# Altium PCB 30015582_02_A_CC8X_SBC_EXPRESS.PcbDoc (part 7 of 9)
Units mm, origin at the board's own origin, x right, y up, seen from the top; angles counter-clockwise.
Board outline 87 x 63 mm, 6 copper layers (Top Layer-L1, GND Plane-L2, Signal-L3, PWR/Signal-L4, GND Plane-L5, Bottom Layer-L6), stack 1.172 mm thick; 169 components, 171 nets, 693 pads, 391 vias.
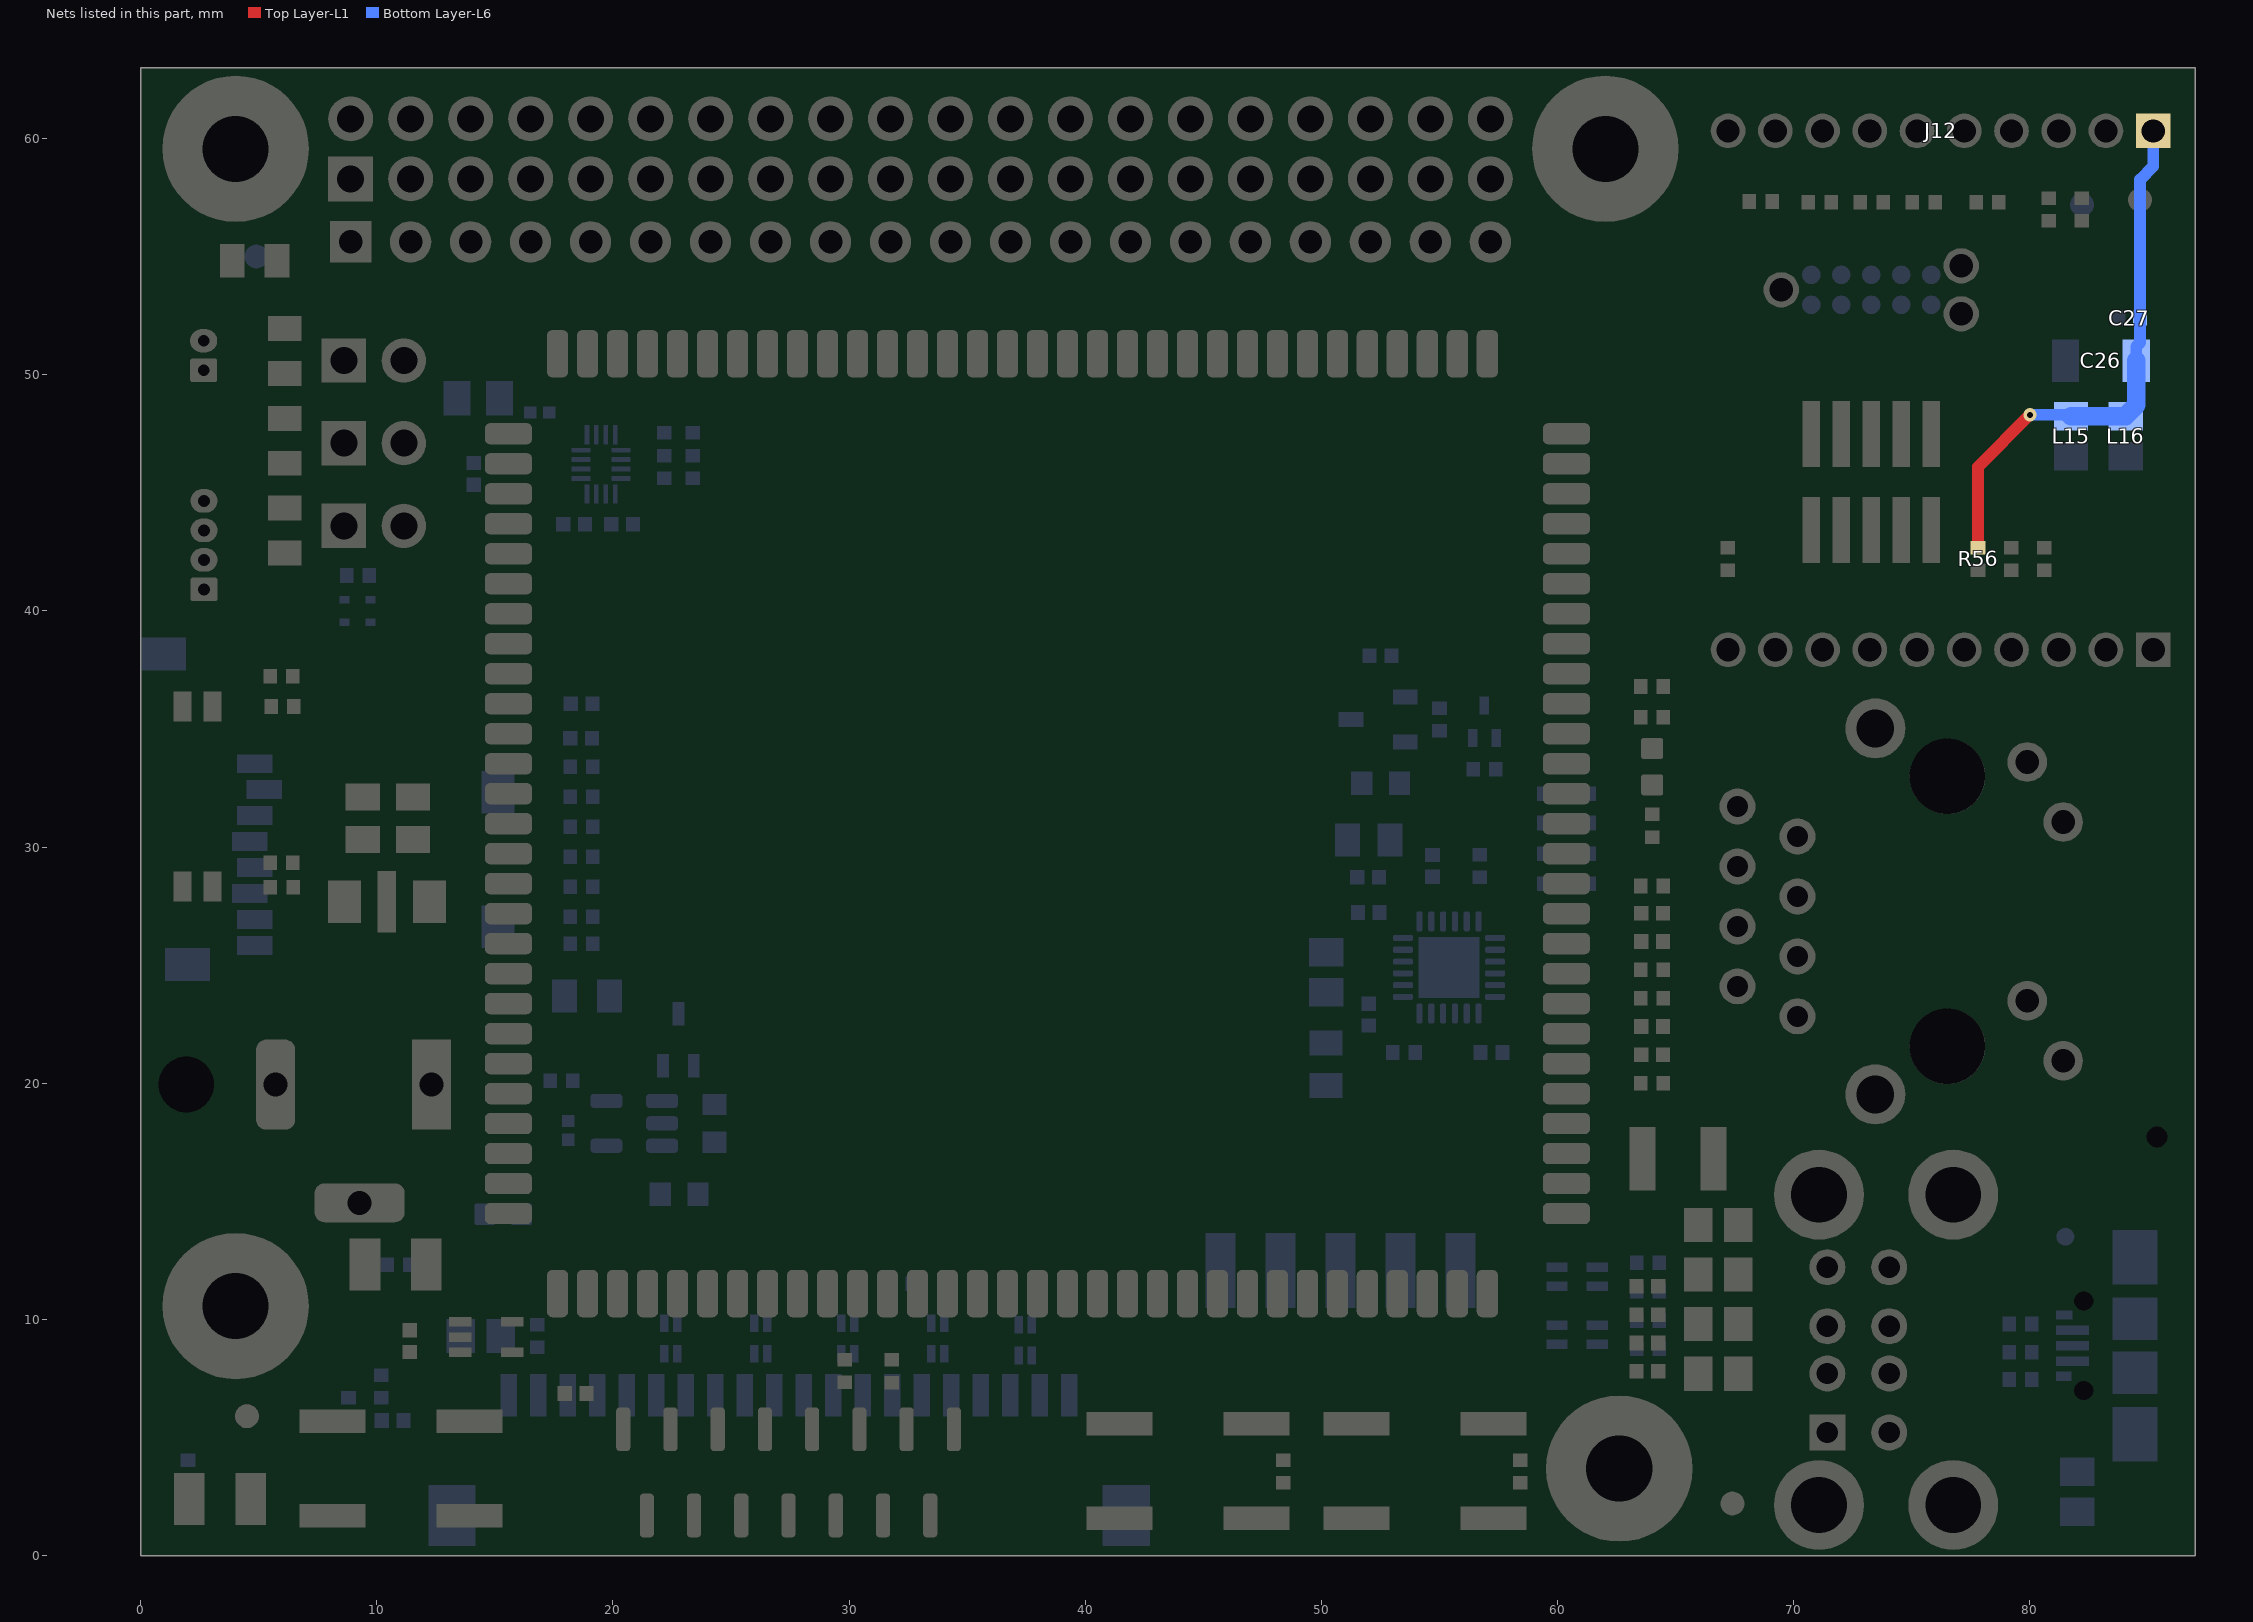
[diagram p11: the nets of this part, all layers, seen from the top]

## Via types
v1: diameter 0.56, hole 0.25, Top Layer-L1 to Bottom Layer-L6, 391 vias

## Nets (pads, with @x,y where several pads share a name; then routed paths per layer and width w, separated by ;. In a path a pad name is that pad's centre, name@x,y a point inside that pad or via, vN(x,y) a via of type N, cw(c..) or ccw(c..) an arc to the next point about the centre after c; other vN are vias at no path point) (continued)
XBEE_VCC: C26.1 C27.2 J12.1 L15.2 L16.2 R56.2 | length 23.5
  Top Layer-L1 w0.5: R56.2@77.8,42.68 77.8,46.1 v1(80,48.3)
  Bottom Layer-L6 w0.5: v1(80,48.3) L15.2@81.984,48.3 ; L15.2@81.684,48.3 L15.2@81.742,48.242 ; C26.1@84.5,50.6 84.5,51.2 84.66,51.36 C27.2@84.66,52.4 84.66,58.26 85.217,58.817 J12.1@85.217,60.325
  Bottom Layer-L6 w0.8: L15.2@81.742,48.242 84.028,48.242 L16.2@84.056,48.27 ; L16.2@84.056,48.242 L16.2@84.056,48.27 ; C26.1@84.5,50.6 84.5,48.714 L16.2@84.056,48.27
pads on no net: FIDUCIAL1.1 FIDUCIAL2.1 FIDUCIAL3.1 FIDUCIAL7.1 FIDUCIAL8.1 FIDUCIAL9.1 J2.3 J2.4 J6.7 J6.MNT1 J6.MNT2 J7.MT1 J7.MT21 J10.10 J10.11 J13.1 J13.2 J13.3 J13.4 J19.6 J19.7 J19.8 SWD.6 SWD.7 SWD.8 SWD.9 SWD.MT1 SWD.MT2 SWD.MT3 U2.11 U2.12 U2.13 U2.14 U2.15 U2.16 U3.4

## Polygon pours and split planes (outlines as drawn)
VCC_SCU_1V8 on Top Layer-L1 "Polysolid" (solid, remove dead copper, pour order 44): 6.2,29.1 6.2,30.232 7.1,31.132 7.1,35.5 6.9,35.7 6.2,35.7 6.2,36.2 7.5,36.2 8.4,37.1 10.8,37.1 10.9,37 10.9,34.7 10.3,34.1 8.6,34.1 8.2,33.7 8.2,31.3 6.7,29.8 6.7,29.1
3V3 on Top Layer-L1 "Polysolid" (solid, remove dead copper, pour order 28): 5.4,43.8 6.5,43.8 7.7,42.6 9.6,42.6 9.6,43.625 10.675,44.7 12,44.7 13.2,45.9 13.2,48.3 13.5,48.6 15.7,48.6 16.5,49.4 16.5,51.6 16.9,52 20.8,52 21.1,51.7 21.1,50.7 21.8,50.7 21.8,51.6 22.4,52.2 22.4,52.5 22.2,52.7 16.2,52.7 15.4,51.9 15.4,50.1 15.2,49.9 12.9,49.9 12.2,49.2 12.2,46.7 11,45.5 10.5,45.5 9.6,44.6 6.9,44.6 6.6,44.9 5.4,44.9
SHLD on Top Layer-L1 "Polysolid" (solid, remove dead copper, pour order 2): 69.8,0.9 77.2,0.9 79.1,2.8 79.1,15.4 77.6,16.9 76.7,16.9 74.8,15 74.8,13.8 77.3,11.3 77.3,6.2 75.2,4.1 71.3,4.1 69.8,2.6
VCC_SCU_1V8 on PWR/Signal-L4 "Polysolid" (solid, remove dead copper, pour order 46): 32,12.1 26,12.1 22.8,15.3 22.8,34.7 21.2,36.3 21.2,41.3 22.2,42.3 26.8,42.3 27.3,41.8 27.3,14.4 27.8,13.9 31.8,13.9 32.1,13.6 32.1,12.2
3V3_EXT on PWR/Signal-L4 "Polysolid" (solid, remove dead copper, pour order 40): 78,41.5 79.9,41.5 82.7,44.3 82.7,47.8 82.2,48.3 76.2,48.3 65,48.3 58.9,48.3 56.5,50.7 20.8,50.7 20.8,53.4 22.2,54.8 30.5,54.8 30.5,62.7 13.35,62.7 13.35,54.35 9.5,50.5 9.5,30.7 10.8,29.4 10.8,12.4 15.7,7.5 40.9,7.5 41.2,7.8 41.2,10.8 40.2,11.8 25.9,11.8 22.4,15.3 22.4,34.5 21,35.9 21,41.5 22.2,42.7 26.8,42.7 27.1,43 27.1,47.6 27.8,48.3 48.3,48.3 49.3,47.3 49.3,39.4 49.9,38.8 52.5,38.8 53,38.3 53,33.3 53.7,32.6 63.4,32.6 64.4,33.6 64.4,41 64.9,41.5 66.1,41.5 66.6,41 66.6,40.2 67.2,39.6 76.8,39.6 77.1,39.9 77.1,40.6
VCC_MCA on PWR/Signal-L4 "Polysolid" (solid, remove dead copper, pour order 36): 76,48.7 67.925,48.7 67.925,51.225 65.325,53.825 60.175,53.825 57.1,56.9 57.1,57.1 59.1,57.1 60.3,55.9 75.5,55.9 76.2,55.2 76.2,48.9
AVDD1 on PWR/Signal-L4 "Polysolid" (solid, remove dead copper, pour order 34): 49.3,21 50.8,19.5 63.8,19.5 65,20.7 65,29.3 64.7,29.6 63.3,29.6 63,29.3 63,24.5 61.5,23 49.5,23 49.3,22.8
3V3 on PWR/Signal-L4 "Polysolid" (solid, remove dead copper, pour order 24): 21.3,51.5 25.756,51.5 26.156,51.9 57.3,51.9 60.5,48.7 66.3,48.7 66.55,48.95 66.55,50.35 64.45,52.45 58.775,52.45 57.987,53.237 52.888,53.238 51.725,54.4 22.4,54.4 21.1,53.1 21.1,51.7
VIN on PWR/Signal-L4 "Polysolid" (solid, remove dead copper, pour order 12): 0.7,1.4 1.5,0.6 80.5,0.6 86.6,6.7 86.6,47.6 86.7,47.6 86.7,57.4 85.7,58.4 75.6,58.4 75.3,58.1 75.3,57.1 76.7,55.7 76.7,49.3 77.3,48.7 82.5,48.7 83.1,48.1 83.1,44.1 79.9,40.9 78.1,40.9 77.6,40.4 77.6,37.4 77.6,35.6 78,35.2 79.8,35.2 82.7,32.3 82.7,15.1 81.3,13.7 60.7,13.7 54.2,7.2 15.4,7.2 10.3,12.3 10.3,29 8.9,30.4 8.9,50.5 11.7,53.3 12.9,54.5 12.9,61.5 11.9,62.5 6.1,62.5 0.7,57.1 0.7,29
3V3_ETH0 on PWR/Signal-L4 "Polysolid" (solid, remove dead copper, pour order 0): 49.275,23.825 49.275,38.025 49.725,38.475 52.45,38.475 52.775,38.15 52.775,32.75 53.275,32.25 61.7,32.25 62.325,31.625 62.325,24.225 61.275,23.175 49.925,23.175
3V3 on Bottom Layer-L6 "Polysolid" (solid, remove dead copper, pour order 48): 64.8,39.6 64.8,49.3 65.2,49.7 66.3,49.7 66.6,49.4 66.6,40.2 65.8,39.4 65,39.4
VCC_SCU_1V8 on Bottom Layer-L6 "Polysolid" (solid, remove dead copper, pour order 42): 9.5,36.4 17.6,36.4 17.8,36.6 19.7,36.6 20.1,36.2 21.8,36.2 22,36.4 22,38.7 21.2,39.5 13.4,39.5 12,38.1 9.5,38.1 9.3,37.9 9.3,36.6
5V_CC8X on Bottom Layer-L6 "Polysolid" (solid, remove dead copper, pour order 26): 10.9,46.5 13.3,46.5 13.6,46.8 15,46.8 15.7,47.5 15.7,49 16.3,49.6 16.9,49.6 17.1,49.4 17.1,48.3 17.5,48.3 17.5,48.9 17.7,49.1 19.1,49.1 19.3,49.3 19.3,49.823 18.923,50.2 16.2,50.2 15.6,49.6 15,49.6 15,48.2 14.8,48 14.2,48 13.6,47.4 12.5,47.4 12.1,47.8 10.9,47.8
XBEE_VCC on Bottom Layer-L6 "Polysolid" (solid, remove dead copper, pour order 50): 79.7,47.7 85,47.7 85.2,47.9 85.2,57.9 85.8,58.5 85.8,60.4 85.4,60.8 84.8,60.8 84.6,60.6 84.6,59.1 84.1,58.6 84.1,53.3 84.4,53 84.4,52.1 83.9,51.6 83.9,49.2 83.6,48.9 79.8,48.9 79.5,48.6 79.5,47.9
GND on GND Plane-L2 (split plane): 86.49,0.51 0.51,0.51 0.51,62.49 86.49,62.49
GND on GND Plane-L5 (split plane): 86.49,0.51 0.51,0.51 0.51,62.49 86.49,62.49

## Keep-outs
Keep-Out Layer:
  lines w0.25: 0,39.45 0,63 87,63 87,0 0,0 0,39.575

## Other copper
Top Layer-L1:
  region net VIN: 11.95,9.25 12.15,9.05 12.15,8.775 12.325,8.6 12.65,8.6 12.8,8.75 12.8,9.575 12.925,9.7 14,9.7 14,10.1 12.05,10.1 11.8,9.85 11.1,9.85 11.1,9.25
  region net 1V8_EXT: 6.075,54.275 6.75,54.95 9.35,54.95 9.35,56.3 6.675,56.3 5.575,55.2 5.575,54.275
  region net VCC_MCA: 0.8,47.2 0.925,47.075 2.85,47.075 4.7,48.925 4.7,50.425 5.9,51.625 5.9,52.45 5.875,52.475 5.35,52.475 3.775,50.9 3.775,49.55 3,48.775 1.025,48.775 0.8,48.55
  region net 3V3_EXT: 2.375,43.9 4,43.9 4.925,42.975 6.775,42.975 7.725,42.025 7.725,41.65 4.825,41.65 3.575,42.9 2.375,42.9 2.1,43.175 2.1,43.625
  region net NetFIL1_1: 11.4,26.3 11.4,29.1 11.6,29.3 12.9,29.3 13.1,29.1 13.1,26.3 12.9,26.1 11.6,26.1
  region net VIN: 7.8,30.5 7.8,26.8 7.9,26.7 9.3,26.7 9.4,26.8 9.4,29.313 9.915,29.828 12.028,29.828 12.2,30 12.2,30.7 8,30.7
  region net GND: 10.059,31.9 10.059,33.3 9.959,33.4 8.859,33.4 8.759,33.3 8.759,31.9
  region net GND: 12.2,31.9 12.2,33.3 12.1,33.4 11,33.4 10.9,33.3 10.9,31.9
  region net GND: 63.75,18.075 62.45,18.075 62.325,17.95 62.325,15.675 62.45,15.55 63.75,15.55
  region net SHLD: 70,17.9 72.9,20.8 73.5,20.8 74.75,19.55 74.75,17.725 75.275,17.2 76.9,17.2 78.1,16 78.1,14.55 76.925,13.375 70.925,13.375 68.6,15.7 66.4,15.7 66.4,17.9
  region net NetFIL1_1: 11.9,18.4 11.6,18.7 11.6,26.5 11.8,26.7 12.8,26.7 13,26.5 13,18.4
  region net GND: 63,10 62.8,10.2 61.7,10.2 61.6,10.3 61.6,10.8 61.7,10.9 62.6,10.9 63.1,11.4 63.6,11.4 63.6,10
  region net GND: 63.6,7.55 61.675,7.55 61.6,7.625 61.6,8.35 61.7,8.45 62.575,8.45 63.15,9.025 63.6,9.025
  text "30015582-02_TOP" at 86.3,40 h1.1 r90
Signal-L3:
  text ".Layer_Name" at 27,-4.175 h2.54
PWR/Signal-L4:
  region net 3V3_EXT: 66.45,48 66.725,48.275 66.725,50.55 64.625,52.65 58.825,52.65 58.05,53.425 54.875,53.425 53.7,54.6 53.7,56.025 54.15,56.475 55.05,56.475 55.425,56.1 55.425,55.5 56.5,54.425 58.5,54.425 59.325,53.6 65.25,53.6 67.7,51.15 67.7,48.25 68.025,47.925
  text ".Layer_Name" at 24.575,-4.325 h2.54
Bottom Layer-L6:
  rectangle net NetJ7_19: 16.55,7.075 17.1,8.85
  region net GND: 82.189,1.4 82.189,2.3 83.089,2.3 83.6,2.811 83.6,14.3 83.8,14.5 86.1,14.5 86.2,14.4 86.2,3.7 83.9,1.4
  region net 3V3_EXT: 52.925,33.45 53.025,33.55 53.025,34.775 53.925,34.775 54.35,35.2 55.3,35.2 55.325,35.175 55.325,34.775 56.5,33.6 56.5,33 54.65,33 53.85,32.2 52.925,32.2
  region net 3V3_ETH0: 49.475,25.325 49.475,26.775 49.575,26.875 50.8,26.875 50.925,26.75 50.925,25.325
  region net AVDD1: 49.5,24 49.5,21.8 50.9,21.8 50.9,24
  text "30015582-02_BOT" at 84.582,20.066 h1.1 r270
  text ".Layer_Name" at 20.864,-4.552 h2.54
GND Plane-L2 (plane layer: these items are gaps in the copper):
  text ".Layer_Name" at 24.689,-4.827 h2.54
  text "Negative Image" at 23.175,-8.05 h2.54
GND Plane-L5 (plane layer: these items are gaps in the copper):
  text ".Layer_Name" at 24.775,-4.75 h2.54
  text "Negative Image" at 23.175,-8.05 h2.54

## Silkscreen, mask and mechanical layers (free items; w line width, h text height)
Top Overlay:
  drawing of 16 lines, arcs and shapes, not listed
  text "COIN CELL" at 4.3,53.5 h1.5 r270
  text "EXPANSION HEADER" at 10.89,53.018 h1.5
  text "CONSOLE" at 4.3,45.4 h1.5 r270
  text "Close" at 8.3,41.5 h1 r270
  text "Close" at 9.4,41.5 h1 r270
  text "Open" at 10.5,41.5 h1 r270
  text "SW1.2" at 11.5,41.5 h1 r270
  text "XBEE MODULE" at 68.1,39.9 h1.5
  text "Close" at 8.3,39.1 h1 r270
  text "Open" at 9.4,39.1 h1 r270
  text "Open" at 10.5,39.1 h1 r270
  text "SW1.1" at 11.5,39.1 h1 r270
  text "USB" at 8.3,36.6 h1 r270
  text "MicroSD" at 9.4,36.6 h1 r270
  text "eMMC" at 10.5,36.6 h1 r270
  text "BOOT" at 11.5,36.4 h1 r270
  text "10/100 ETH" at 66.04,35.56 h1.5
  text "BOOT" at 4.826,33.528 h1.5 r270
  text "PWR - 5V" at 0.762,25.019 h1.5
  text "5VDC" at 1.406,19.637 h1.4
  text "USB HOST" at 79.248,15.621 h1.5
  text "ConnectCore for i.MX8X SOM" at 18.639,8.763 h1.5
  text "RESET" at 42.568,7.255 h1.5
  text "ON/OFF" at 52.705,7.239 h1.5
  text "USER  BUTTON" at 7.75,6.975 h1.5
  text "MIPI DSI" at 35.022,5.885 h1.5
  text "USER LED" at 1.6,3.8 h1.5
Bottom Overlay:
  text "MICRO SD" at 16.383,39.37 h1.5
  text "USB DEVICE" at 85.5,14.8 h1.5
  text "Touch controller" at 58,14.1 h1.5
  text "LVDS" at 20.9,8.6 h1.5
  text ".Layer_Name" at 20.864,-4.552 h2.54
Top Paste:
  text ".Layer_Name" at 20.864,-4.552 h2.54
Bottom Paste:
  text ".Layer_Name" at 20.864,-4.552 h2.54
Top Solder:
  text ".Layer_Name" at 20.864,-4.552 h2.54
Bottom Solder:
  text ".Layer_Name" at 20.864,-4.552 h2.54
Board Outline:
  the board outline again, w0.2
Top Assembly:
  drawing of 53 lines, arcs and shapes, not listed
  text "1. Manufacture in accordance with IPC-6012, class 2. Inspect to IPC-A-600, class 2." at -17.381,81.17 h3.17
  text ".Layer_Name" at 20.864,-4.552 h2.54
  text "CAD GENERATED:" at 52.68,-9.22 h1.27
  text ".pcb_File_Name_No_Path" at 68.174,-9.22 h2.17
  text "EXCEPT AS MAY BE OTHERWISE PROVIDED BY" at -46.38,-13.284 h2.17
  text "WIRELESS DESIGN SERVICES" at 47.6,-14.808 h2.54
  text "CONTRACT, THIS DOCUMENT IS THE PROPERTY" at -46.38,-15.316 h2.17
  text "OF DIGI INTERNATIONAL.  IF RELEASED TO OTHER" at -46.38,-17.348 h2.17
  text "11001 Bren Road East" at 47.6,-18.364 h2.54
  text "SOURCES, IT SHALL BE RECEIVED BY SUCH" at -46.38,-19.38 h2.17
  text "SOURCES IN TOTAL CONFIDENCE AND SHALL NOT" at -46.38,-21.412 h2.17
  text "Minnetonka, MN 55343" at 48.108,-21.92 h2.54
  text "BE RELEASED TO ANY THIRD PARTY OR PARTIES," at -46.38,-23.444 h2.17
  text "NOR USED FOR MANUFACTURE OR SALE OF THE" at -46.38,-25.476 h2.17
  text "ARTICLES WITHOUT PRIOR WRITTEN" at -46.38,-27.508 h2.17
  text "DIGI International" at 39.123,-27.775 h2.54
  text "AUTHORIZATION." at -46.38,-29.54 h2.17
  text "Connect Core 8X" at 36.998,-31.625 h2.54
  text "SBC EXPRESS" at 40.259,-35.687 h2.54
  text "ENGINEER" at -46.888,-36.144 h1.27
  text "J.Anzola" at -30.124,-37.16 h1.27
  text "PCB DESIGNER" at -46.888,-41.224 h1.27
  text "SIZE" at 6.452,-41.224 h1.27
  text "CAGE NO." at 14.58,-41.224 h1.27
  text "PCB NO." at 42.52,-41.224 h1.27
  text "REV." at 104.496,-41.224 h1.27
  text "DIGI: 55002011-01" at 54.133,-43.04 h2.54
  text "DATE" at -46.888,-45.796 h1.27
  text "B" at 6.96,-45.796 h2.54
  text ".VariantRevision" at 104.496,-45.796 h2.54
  text ".Print_Date" at -30.124,-46.812 h1.27
  text "JIRA EPIC:" at -46.888,-50.876 h1.27
  text "CC8X-10" at -30.124,-52.4 h1.27
  text ".Print_Scale" at 4.42,-52.4 h1.27
  text "SVN HEAD REV:" at 29.82,-52.4 h1.27
  text ".VersionControl_RevNumber" at 45.568,-52.4 h1.27
  text "SHEET:" at 67.92,-52.4 h1.27
  text "1 OF 2" at 86.462,-52.4 h1.27
Bottom Assembly:
  drawing of 53 lines, arcs and shapes, not listed
  text "CUTOUT" at 45.085,41.402 h1.91
  text ".Layer_Name" at 57.785,-4.445 h2.54
  text ".pcb_File_Name_No_Path" at -4.318,-9.525 h2.17
  text "CAD GENERATED:" at 11.176,-9.525 h1.27
  text "EXCEPT AS MAY BE OTHERWISE PROVIDED BY" at 110.236,-13.589 h2.17
  text "WIRELESS DESIGN SERVICES" at 16.256,-15.113 h2.54
  text "CONTRACT, THIS DOCUMENT IS THE PROPERTY" at 110.236,-15.621 h2.17
  text "OF DIGI INTERNATIONAL.  IF RELEASED TO OTHER" at 110.236,-17.653 h2.17
  text "11001 Bren Road East" at 16.256,-18.669 h2.54
  text "SOURCES, IT SHALL BE RECEIVED BY SUCH" at 110.236,-19.685 h2.17
  text "SOURCES IN TOTAL CONFIDENCE AND SHALL NOT" at 110.236,-21.717 h2.17
  text "Minnetonka, MN 55343" at 15.748,-22.225 h2.54
  text "BE RELEASED TO ANY THIRD PARTY OR PARTIES," at 110.236,-23.749 h2.17
  text "NOR USED FOR MANUFACTURE OR SALE OF THE" at 110.236,-25.781 h2.17
  text "ARTICLES WITHOUT PRIOR WRITTEN" at 110.236,-27.813 h2.17
  text "DIGI International" at 24.732,-28.08 h2.54
  text "AUTHORIZATION." at 110.236,-29.845 h2.17
  text "Connect Core 8X" at 25.781,-32.004 h2.54
  text "SBC EXPRESS" at 22.479,-36.068 h2.54
  text "ENGINEER" at 110.744,-36.449 h1.27
  text "J.Anzola" at 93.98,-37.465 h1.27
  text "REV." at -40.64,-41.529 h1.27
  text "PCB NO." at 21.336,-41.529 h1.27
  text "CAGE NO." at 49.276,-41.529 h1.27
  text "SIZE" at 57.404,-41.529 h1.27
  text "PCB DESIGNER" at 110.744,-41.529 h1.27
  text "DIGI: 55002011-01" at 9.722,-43.345 h2.54
  text ".VariantRevision" at -40.64,-46.101 h2.54
  text "B" at 56.896,-46.101 h2.54
  text "DATE" at 110.744,-46.101 h1.27
  text ".Print_Date" at 93.98,-47.117 h1.27
  text "JIRA EPIC:" at 110.744,-51.181 h1.27
  text "SHEET:" at -4.064,-52.705 h1.27
  text ".VersionControl_RevNumber" at 18.288,-52.705 h1.27
  text "SVN HEAD REV:" at 34.036,-52.705 h1.27
  text ".Print_Scale" at 59.436,-52.705 h1.27
  text "CC8X-10" at 93.98,-52.705 h1.27
  text "2 of 2" at -22.428,-52.883 h1.27
PCB Name:
  text "CC8X SBC Express" at 18.5,69.9 h2.54
Sheet Graphics:
  drawing of 499 lines, arcs and shapes, not listed
  text "2" at 44.774,94.272 h4.57
  text "1" at 260.674,94.272 h4.57
  text "1. Manufacture in accordance with IPC-6012, class 2. Inspect to IPC-A-600, class 2." at 190,88 h4.44
  text "2. Manufacturing process and materials used must comply with / ROHS directive 2002/95/EC." at 190,78 h4.44
  text "3. Laminate and prepreg shall be per IPC-4101/126 / Dk shall be 4.2-4.5, Tg of 170°C or higher. / Material thicknesses and dielectric constant are critical items." at 190,64 h4.44
  text "4. Top and Bottom layer starting copper weight is 1 oz." at 190,58 h4.44
  text "5. Apply E.N.I.G. to all exposed copper per IPC-4552." at 190,52 h4.44
  text "6. Solder mask registration shall be ±25.4µm (1mil). Thickness / not to exceed 20.32µm (0.8mil). / COLOR: BLUE" at 190,38 h4.44
  text "B" at -58.299,33.058 h7.11
  text "B" at 357.753,33.058 h7.11
  text "7. Silkscreen Color: White silkscreen that encroaches on component pads." at 190,32 h4.44
  text "8. Gerber file format: 274-X with 2/4 accuracy (XX.XXXX) / Gerber and drill files generated in inches." at 190,22 h4.44
  text "9. Maximum warp and twist per IPC-6012 of 0.75% inch/inch." at 190,18 h4.44
  text "10. Vendor markings to appear on silkscreen or solder mask layers only." at 188,14 h4.44
  text "11. All boards to be 100% electrically tested." at 188,10 h4.44
  text "12. Copper thieving is not allowed within board outline.  Thieving may be placed in the array." at 188,6 h4.44
  text "13. Panel array to be approved by Digi." at 188,2 h4.44
  text "14. All drilled holes are specified as finished hole size." at 188,-2 h4.44
  text "15. Slot/Cutout tolerance ±0.005 inch when applicable." at 188,-6 h4.44
  text "16. Controlled Impedances listed in table." at 188.539,-11.365 h4.44
  text "17.  All via/plated holes have a tolerance of ±76.2µm (3mil) unless otherwise specified. / Non-plated holes have a ±38.1µm tolerance unless otherwise specified." at 188,-22 h4.44
  text "18.  Total thickness is 47.5mil (1.2mm) +/- 10%." at 188,-26 h4.44
  text "19.  PCB material shall be IT-180A" at 188,-32 h4.44
  text "T" at 163.048,-44.431 h6.02
  text "r" at 165.461,-44.431 h6.02
  text "a" at 167.186,-44.431 h6.02
  text "c" at 169.599,-44.431 h6.02
  text "e" at 171.668,-44.431 h6.02
  text "l" at 175.461,-44.431 h6.02
  text "a" at 176.841,-44.431 h6.02
  text "y" at 179.255,-44.431 h6.02
  text "e" at 181.668,-44.431 h6.02
  text "r" at 184.427,-44.431 h6.02
  text "R" at 187.981,-44.431 h6.02
  text "e" at 190.739,-44.431 h6.02
  text "f" at 193.498,-44.431 h6.02
  text "e" at 195.222,-44.431 h6.02
  text "r" at 197.981,-44.431 h6.02
  text "e" at 199.705,-44.431 h6.02
  text "n" at 202.463,-44.431 h6.02
  text "c" at 205.222,-44.431 h6.02
  text "e" at 207.291,-44.431 h6.02
  text "l" at 211.084,-44.431 h6.02
  text "a" at 212.463,-44.431 h6.02
  text "y" at 214.877,-44.431 h6.02
  text "e" at 217.291,-44.431 h6.02
  text "r" at 220.05,-44.431 h6.02
  text "(" at 221.774,-44.431 h6.02
  text "s" at 223.498,-44.431 h6.02
  text ")" at 225.567,-44.431 h6.02
  text "I" at 229.189,-44.431 h6.02
  text "m" at 230.569,-44.431 h6.02
  text "p" at 234.706,-44.431 h6.02
  text "e" at 237.465,-44.431 h6.02
  text "d" at 240.224,-44.431 h6.02
  text "a" at 242.982,-44.431 h6.02
  text "n" at 245.396,-44.431 h6.02
  text "c" at 248.155,-44.431 h6.02
  text "e" at 250.224,-44.431 h6.02
  text "(" at 254.017,-44.431 h6.02
  text "Ω" at 255.741,-44.431 h6.02
  text ")" at 259.189,-44.431 h6.02
  text "W" at 263.818,-44.431 h6.02
  text "1" at 268.646,-44.431 h6.02
  text "(" at 272.094,-44.431 h6.02
  text "m" at 273.818,-44.431 h6.02
  text "m" at 277.956,-44.431 h6.02
  text ")" at 282.094,-44.431 h6.02
  text "S" at 287.02,-44.431 h6.02
  text "1" at 289.434,-44.431 h6.02
  text "(" at 292.882,-44.431 h6.02
  text "m" at 294.606,-44.431 h6.02
  text "m" at 298.744,-44.431 h6.02
  text ")" at 302.882,-44.431 h6.02
  text "D" at 307.797,-44.431 h6.02
  text "1" at 310.901,-44.431 h6.02
  text "(" at 314.349,-44.431 h6.02
  text "m" at 316.073,-44.431 h6.02
  text "m" at 320.211,-44.431 h6.02
  text ")" at 324.349,-44.431 h6.02
  text "1" at 183.825,-51.328 h6.02
  text "2" at 206.68,-51.328 h6.02
  text "5" at 229.189,-51.328 h6.02
  text "0" at 231.603,-51.328 h6.02
  text "+" at 234.017,-51.328 h6.02
  text "/" at 236.431,-51.328 h6.02
  text "-" at 238.5,-51.328 h6.02
  text "1" at 240.224,-51.328 h6.02
  text "0" at 242.638,-51.328 h6.02
  text "%" at 245.051,-51.328 h6.02
  text "0" at 274.207,-51.328 h6.02
  text "." at 276.621,-51.328 h6.02
  text "1" at 278,-51.328 h6.02
  text "6" at 280.414,-51.328 h6.02
  text "5" at 282.828,-51.328 h6.02
  text "16" at 144.78,-55.88 h4.44
  text "3" at 183.825,-58.224 h6.02
  text "2" at 206.68,-58.224 h6.02
  text "5" at 229.189,-58.224 h6.02
  text "0" at 231.603,-58.224 h6.02
  text "+" at 234.017,-58.224 h6.02
  text "/" at 236.431,-58.224 h6.02
  text "-" at 238.5,-58.224 h6.02
  text "1" at 240.224,-58.224 h6.02
  text "0" at 242.638,-58.224 h6.02
  text "%" at 245.051,-58.224 h6.02
  text "0" at 274.207,-58.224 h6.02
  text "." at 276.621,-58.224 h6.02
  text "1" at 278,-58.224 h6.02
  text "2" at 280.414,-58.224 h6.02
  text "2" at 282.828,-58.224 h6.02
  text "6" at 183.825,-65.121 h6.02
  text "5" at 206.68,-65.121 h6.02
  text "5" at 229.189,-65.121 h6.02
  text "0" at 231.603,-65.121 h6.02
  text "+" at 234.017,-65.121 h6.02
  text "/" at 236.431,-65.121 h6.02
  text "-" at 238.5,-65.121 h6.02
  text "1" at 240.224,-65.121 h6.02
  text "0" at 242.638,-65.121 h6.02
  text "%" at 245.051,-65.121 h6.02
  text "0" at 274.207,-65.121 h6.02
  text "." at 276.621,-65.121 h6.02
  text "1" at 278,-65.121 h6.02
  text "6" at 280.414,-65.121 h6.02
  text "5" at 282.828,-65.121 h6.02
  text "1" at 183.825,-72.017 h6.02
  text "2" at 206.68,-72.017 h6.02
  text "9" at 229.189,-72.017 h6.02
  text "0" at 231.603,-72.017 h6.02
  text "+" at 234.017,-72.017 h6.02
  text "/" at 236.431,-72.017 h6.02
  text "-" at 238.5,-72.017 h6.02
  text "1" at 240.224,-72.017 h6.02
  text "0" at 242.638,-72.017 h6.02
  text "%" at 245.051,-72.017 h6.02
  text "0" at 274.207,-72.017 h6.02
  text "." at 276.621,-72.017 h6.02
  text "1" at 278,-72.017 h6.02
  text "2" at 280.414,-72.017 h6.02
  text "7" at 282.828,-72.017 h6.02
  text "0" at 294.985,-72.017 h6.02
  text "." at 297.398,-72.017 h6.02
  text "1" at 298.778,-72.017 h6.02
  text "2" at 301.191,-72.017 h6.02
  text "7" at 303.605,-72.017 h6.02
  text "LAYER STACK TABLE" at -33.23,-78.155 h4.44
  text "3" at 183.825,-78.914 h6.02
  text "2" at 206.68,-78.914 h6.02
  text "9" at 229.189,-78.914 h6.02
  text "0" at 231.603,-78.914 h6.02
  text "+" at 234.017,-78.914 h6.02
  text "/" at 236.431,-78.914 h6.02
  text "-" at 238.5,-78.914 h6.02
  text "1" at 240.224,-78.914 h6.02
  text "0" at 242.638,-78.914 h6.02
  text "%" at 245.051,-78.914 h6.02
  text "0" at 274.207,-78.914 h6.02
  text "." at 276.621,-78.914 h6.02
  text "1" at 278,-78.914 h6.02
  text "0" at 280.414,-78.914 h6.02
  text "2" at 282.828,-78.914 h6.02
  text "0" at 294.985,-78.914 h6.02
  text "." at 297.398,-78.914 h6.02
  text "1" at 298.778,-78.914 h6.02
  text "5" at 301.191,-78.914 h6.02
  text "2" at 303.605,-78.914 h6.02
  text "Layer" at -31.88,-82.902 h1.52
  text "Name" at -21.468,-82.902 h1.52
  text "Material" at 3.925,-82.902 h1.52
  text "Thickness" at 25.763,-82.902 h1.52
  text "Constant" at 42.269,-82.902 h1.52
  text "Board Layer Stack" at 56.743,-82.902 h1.52
  text "6" at 183.825,-85.811 h6.02
  text "5" at 206.68,-85.811 h6.02
  text "9" at 229.189,-85.811 h6.02
  text "0" at 231.603,-85.811 h6.02
  text "+" at 234.017,-85.811 h6.02
  text "/" at 236.431,-85.811 h6.02
  text "-" at 238.5,-85.811 h6.02
  text "1" at 240.224,-85.811 h6.02
  text "0" at 242.638,-85.811 h6.02
  text "%" at 245.051,-85.811 h6.02
  text "0" at 274.207,-85.811 h6.02
  text "." at 276.621,-85.811 h6.02
  text "1" at 278,-85.811 h6.02
  text "2" at 280.414,-85.811 h6.02
  text "7" at 282.828,-85.811 h6.02
  text "0" at 294.985,-85.811 h6.02
  text "." at 297.398,-85.811 h6.02
  text "1" at 298.778,-85.811 h6.02
  text "2" at 301.191,-85.811 h6.02
  text "7" at 303.605,-85.811 h6.02
  text "1" at -31.88,-85.95 h1.52
  text "Top Overlay" at -21.468,-85.95 h1.52
  text "2" at -31.88,-88.998 h1.52
  text "Top Solder" at -21.468,-88.998 h1.52
  text "Solder Resist" at 3.925,-88.998 h1.52
  text "0.40mil" at 25.763,-88.998 h1.52
  text "3.5" at 42.269,-88.998 h1.52
  text "3" at -31.88,-92.046 h1.52
  text "Top Layer-L1" at -21.468,-92.046 h1.52
  text "Copper" at 3.925,-92.046 h1.52
  text "1.89mil" at 25.763,-92.046 h1.52
  text "1" at 183.825,-92.707 h6.02
  text "2" at 206.68,-92.707 h6.02
  text "1" at 229.189,-92.707 h6.02
  text "0" at 231.603,-92.707 h6.02
  text "0" at 234.017,-92.707 h6.02
  text "+" at 236.431,-92.707 h6.02
  text "/" at 238.844,-92.707 h6.02
  text "-" at 240.913,-92.707 h6.02
  text "1" at 242.638,-92.707 h6.02
  text "0" at 245.051,-92.707 h6.02
  text "%" at 247.465,-92.707 h6.02
  text "0" at 274.207,-92.707 h6.02
  text "." at 276.621,-92.707 h6.02
  text "1" at 278,-92.707 h6.02
  text "1" at 280.414,-92.707 h6.02
  text "4" at 282.828,-92.707 h6.02
  text "0" at 294.985,-92.707 h6.02
  text "." at 297.398,-92.707 h6.02
  text "1" at 298.778,-92.707 h6.02
  text "7" at 301.191,-92.707 h6.02
  text "8" at 303.605,-92.707 h6.02
  text "4" at -31.88,-95.094 h1.52
  text "Dielectric 1" at -21.468,-95.094 h1.52
  text "FR-4" at 3.925,-95.094 h1.52
  text "4.92mil" at 25.763,-95.094 h1.52
  text "4.2" at 42.269,-95.094 h1.52
  text "5" at -31.88,-98.142 h1.52
  text "GND Plane-L2" at -21.468,-98.142 h1.52
  text "Copper" at 3.925,-98.142 h1.52
  text "1.10mil" at 25.763,-98.142 h1.52
  text "3" at 183.825,-99.604 h6.02
  text "2" at 206.68,-99.604 h6.02
  text "1" at 229.189,-99.604 h6.02
  text "0" at 231.603,-99.604 h6.02
  text "0" at 234.017,-99.604 h6.02
  text "+" at 236.431,-99.604 h6.02
  text "/" at 238.844,-99.604 h6.02
  text "-" at 240.913,-99.604 h6.02
  text "1" at 242.638,-99.604 h6.02
  text "0" at 245.051,-99.604 h6.02
  text "%" at 247.465,-99.604 h6.02
  text "0" at 274.207,-99.604 h6.02
  text "." at 276.621,-99.604 h6.02
  text "1" at 278,-99.604 h6.02
  text "0" at 280.414,-99.604 h6.02
  text "2" at 282.828,-99.604 h6.02
  text "0" at 294.985,-99.604 h6.02
  text "." at 297.398,-99.604 h6.02
  text "2" at 298.778,-99.604 h6.02
  text "5" at 301.191,-99.604 h6.02
  text "4" at 303.605,-99.604 h6.02
  text "6" at -31.88,-101.19 h1.52
  text "Dielectric 4" at -21.468,-101.19 h1.52
  text "FR-4" at 3.925,-101.19 h1.52
  text "4.00mil" at 25.763,-101.19 h1.52
  text "4" at 42.269,-101.19 h1.52
  text "7" at -31.88,-104.238 h1.52
  text "Signal-L3" at -21.468,-104.238 h1.52
  text "Copper" at 3.925,-104.238 h1.52
  text "1.10mil" at 25.763,-104.238 h1.52
  text "6" at 183.825,-106.5 h6.02
  text "5" at 206.68,-106.5 h6.02
  text "1" at 229.189,-106.5 h6.02
  text "0" at 231.603,-106.5 h6.02
  text "0" at 234.017,-106.5 h6.02
  text "+" at 236.431,-106.5 h6.02
  text "/" at 238.844,-106.5 h6.02
  text "-" at 240.913,-106.5 h6.02
  text "1" at 242.638,-106.5 h6.02
  text "0" at 245.051,-106.5 h6.02
  text "%" at 247.465,-106.5 h6.02
  text "0" at 274.207,-106.5 h6.02
  text "." at 276.621,-106.5 h6.02
  text "1" at 278,-106.5 h6.02
  text "1" at 280.414,-106.5 h6.02
  text "4" at 282.828,-106.5 h6.02
  text "0" at 294.985,-106.5 h6.02
  text "." at 297.398,-106.5 h6.02
  text "1" at 298.778,-106.5 h6.02
  text "7" at 301.191,-106.5 h6.02
  text "8" at 303.605,-106.5 h6.02
  text "A" at -58.299,-106.642 h7.11
  text "A" at 357.753,-106.642 h7.11
  text "8" at -31.88,-107.286 h1.52
  text "Dielectric 5" at -21.468,-107.286 h1.52
  text "FR-4" at 3.925,-107.286 h1.52
  text "20.14mil" at 25.763,-107.286 h1.52
  text "4.55" at 42.269,-107.286 h1.52
  text "9" at -31.88,-110.334 h1.52
  text "PWR/Signal-L4" at -21.468,-110.334 h1.52
  text "Copper" at 3.925,-110.334 h1.52
  text "1.10mil" at 25.763,-110.334 h1.52
  text "10" at -31.88,-113.382 h1.52
  text "Dielectric 2" at -21.468,-113.382 h1.52
  text "4.00mil" at 25.763,-113.382 h1.52
  text "4" at 42.269,-113.382 h1.52
  text "11" at -31.88,-116.43 h1.52
  text "GND Plane-L5" at -21.468,-116.43 h1.52
  text "Copper" at 3.925,-116.43 h1.52
  text "1.10mil" at 25.763,-116.43 h1.52
  text "12" at -31.88,-119.478 h1.52
  text "Dielectric 3" at -21.468,-119.478 h1.52
  text "4.92mil" at 25.763,-119.478 h1.52
  text "4.2" at 42.269,-119.478 h1.52
  text "CAD GENERATED:" at 294.456,-121.12 h1.27
  text ".pcb_File_Name_No_Path" at 309.95,-121.12 h2.17
  text "13" at -31.88,-122.526 h1.52
  text "Bottom Layer-L6" at -21.468,-122.526 h1.52
  text "Copper" at 3.925,-122.526 h1.52
  text "1.89mil" at 25.763,-122.526 h1.52
  text "EXCEPT AS MAY BE OTHERWISE PROVIDED BY" at 195.396,-125.184 h2.17
  text "14" at -31.88,-125.574 h1.52
  text "Bottom Solder" at -21.468,-125.574 h1.52
  text "Solder Resist" at 3.925,-125.574 h1.52
  text "0.40mil" at 25.763,-125.574 h1.52
  text "3.5" at 42.269,-125.574 h1.52
  text "WIRELESS DESIGN SERVICES" at 289.376,-126.708 h2.54
  text "CONTRACT, THIS DOCUMENT IS THE PROPERTY" at 195.396,-127.216 h2.17
  text "15" at -31.88,-128.622 h1.52
  text "Bottom Overlay" at -21.468,-128.622 h1.52
  text "OF DIGI INTERNATIONAL.  IF RELEASED TO OTHER" at 195.396,-129.248 h2.17
  text "11001 Bren Road East" at 289.376,-130.264 h2.54
  text "SOURCES, IT SHALL BE RECEIVED BY SUCH" at 195.396,-131.28 h2.17
  text "SOURCES IN TOTAL CONFIDENCE AND SHALL NOT" at 195.396,-133.312 h2.17
  text "Minnetonka, MN 55343" at 289.884,-133.82 h2.54
  text "BE RELEASED TO ANY THIRD PARTY OR PARTIES," at 195.396,-135.344 h2.17
  text "NOR USED FOR MANUFACTURE OR SALE OF THE" at 195.396,-137.376 h2.17
  text "ARTICLES WITHOUT PRIOR WRITTEN" at 195.396,-139.408 h2.17
  text "DIGI International" at 280.9,-139.675 h2.54
  text "AUTHORIZATION." at 195.396,-141.44 h2.17
  text "Connect Core 8X" at 282.75,-143.55 h2.54
  text "SBC Express" at 285.875,-147.875 h2.54
  text "ENGINEER" at 194.888,-148.044 h1.27
  text "S. Meyer" at 211.652,-149.06 h1.27
  text "PCB DESIGNER" at 194.888,-153.124 h1.27
  text "SIZE" at 248.228,-153.124 h1.27
  text "CAGE NO." at 256.356,-153.124 h1.27
  text "PCB NO." at 284.296,-153.124 h1.27
  text "REV." at 346.272,-153.124 h1.27
  text "Larsen/Flagstad" at 211.652,-154.14 h1.27
  text "DIGI: 30015582-02_A" at 295.91,-154.94 h2.54
  text "DATE" at 194.888,-157.696 h1.27
  text "B" at 248.736,-157.696 h2.54
  text "A" at 346.272,-157.696 h2.54
  text ".Print_Date" at 211.652,-158.712 h1.27
  text "JIRA EPIC:" at 194.888,-162.776 h1.27
  text ".Print_Scale" at 246.196,-164.3 h1.27
  text "SVN HEAD REV:" at 271.596,-164.3 h1.27
  text ".VersionControl_RevNumber" at 287.344,-164.3 h1.27
  text "SHEET:" at 309.696,-164.3 h1.27
  text "1 OF 1" at 328.238,-164.3 h1.27
  text "2" at 44.774,-170.777 h4.57
  text "1" at 260.674,-170.777 h4.57
Drill Drawing:
  drawing of 157 lines, arcs and shapes, not listed
  text ".Layer_Name" at 24.13,-4.445 h2.54
  text "Symbol" at -40.798,-12.894 h1.17
  text "Count" at -32.26,-12.894 h1.17
  text "Hole Size" at -22.298,-12.894 h1.17
  text "Plated" at -3.373,-12.894 h1.17
  text "Hole Type" at 5.166,-12.894 h1.17
  text "Drill Layer Pair" at 17.42,-12.894 h1.17
  text "Via/Pad" at 47.917,-12.894 h1.17
  text "Pad Shape" at 57.825,-12.894 h1.17
  text "Template" at 70.275,-12.894 h1.17
  text "Description" at 81.16,-12.894 h1.17
  text "Hole Tolerance (+)" at 95.37,-12.894 h1.17
  text "Hole Tolerance (-)" at 117.404,-12.894 h1.17
  text "1" at -32.26,-15.34 h0.98
  text "0.900mm (35.43mil)" at -22.298,-15.34 h0.98
  text "NPTH" at -3.373,-15.34 h0.98
  text "Round" at 5.166,-15.34 h0.98
  text "Top Layer-L1 - Bottom Layer-L6" at 17.42,-15.34 h0.98
  text "Pad" at 47.917,-15.34 h0.98
  text "Rounded" at 57.825,-15.34 h0.98
  text "c60hn90" at 70.275,-15.34 h0.98
  text "1" at -32.26,-17.785 h0.98
  text "2.362mm (93.00mil)" at -22.298,-17.785 h0.98
  text "NPTH" at -3.373,-17.785 h0.98
  text "Round" at 5.166,-17.785 h0.98
  text "Top Layer-L1 - Bottom Layer-L6" at 17.42,-17.785 h0.98
  text "Pad" at 47.917,-17.785 h0.98
  text "Rounded" at 57.825,-17.785 h0.98
  text "c0hn236" at 70.275,-17.785 h0.98
  text "2" at -32.26,-20.231 h0.98
  text "0.813mm (32.00mil)" at -22.298,-20.231 h0.98
  text "NPTH" at -3.373,-20.231 h0.98
  text "Round" at 5.166,-20.231 h0.98
  text "Top Layer-L1 - Bottom Layer-L6" at 17.42,-20.231 h0.98
  text "Pad" at 47.917,-20.231 h0.98
  text "Rounded" at 57.825,-20.231 h0.98
  text "c0hn81" at 70.275,-20.231 h0.98
  text "L" at -41.335,-20.484 h1.09
  text "2" at -32.26,-22.676 h0.98
  text "1.600mm (63.00mil)" at -22.298,-22.676 h0.98
  text "PTH" at -3.373,-22.676 h0.98
  text "Round" at 5.166,-22.676 h0.98
  text "Top Layer-L1 - Bottom Layer-L6" at 17.42,-22.676 h0.98
  text "Pad" at 47.917,-22.676 h0.98
  text "Rounded" at 57.825,-22.676 h0.98
  text "c254h160" at 70.275,-22.676 h0.98
  text "2" at -32.26,-25.122 h0.98
  text "3.200mm (126.00mil)" at -22.298,-25.122 h0.98
  text "NPTH" at -3.373,-25.122 h0.98
  text "Round" at 5.166,-25.122 h0.98
  text "Top Layer-L1 - Bottom Layer-L6" at 17.42,-25.122 h0.98
  text "Pad" at 47.917,-25.122 h0.98
  text "Rounded" at 57.825,-25.122 h0.98
  text "c320hn320" at 70.275,-25.122 h0.98
  text "3" at -32.26,-27.567 h0.98
  text "1.000mm (39.37mil)" at -22.298,-27.567 h0.98
  text "NPTH" at -3.373,-27.567 h0.98
  text "Round" at 5.166,-27.567 h0.98
  text "Top Layer-L1 - Bottom Layer-L6" at 17.42,-27.567 h0.98
  text "Pad" at 47.917,-27.567 h0.98
  text "Rounded" at 57.825,-27.567 h0.98
  text "c150hn100" at 70.275,-27.567 h0.98
  text "3" at -32.26,-30.013 h0.98
  text "1.016mm (40.00mil)" at -22.298,-30.013 h0.98
  text "PTH" at -3.373,-30.013 h0.98
  text "Slot" at 5.166,-30.013 h0.98
  text "Top Layer-L1 - Bottom Layer-L6" at 17.42,-30.013 h0.98
  text "Pad" at 47.917,-30.013 h0.98
  text "Rectangle" at 57.825,-30.013 h0.98
  text "(Mixed)" at 70.275,-30.013 h0.98
  text "4" at -32.26,-32.458 h0.98
  text "2.362mm (93.00mil)" at -22.298,-32.458 h0.98
  text "PTH" at -3.373,-32.458 h0.98
  text "Round" at 5.166,-32.458 h0.98
  text "Top Layer-L1 - Bottom Layer-L6" at 17.42,-32.458 h0.98
  text "Pad" at 47.917,-32.458 h0.98
  text "Rounded" at 57.825,-32.458 h0.98
  text "c381h236" at 70.275,-32.458 h0.98
  text "E" at -41.335,-32.712 h1.09
  text "4" at -32.26,-34.904 h0.98
  text "2.800mm (110.24mil)" at -22.298,-34.904 h0.98
  text "PTH" at -3.373,-34.904 h0.98
  text "Round" at 5.166,-34.904 h0.98
  text "Top Layer-L1 - Bottom Layer-L6" at 17.42,-34.904 h0.98
  text "Pad" at 47.917,-34.904 h0.98
  text "Rounded" at 57.825,-34.904 h0.98
  text "c620h280" at 70.275,-34.904 h0.98
  text "6" at -32.26,-37.349 h0.98
  text "0.500mm (19.69mil)" at -22.298,-37.349 h0.98
  text "PTH" at -3.373,-37.349 h0.98
  text "Round" at 5.166,-37.349 h0.98
  text "Top Layer-L1 - Bottom Layer-L6" at 17.42,-37.349 h0.98
  text "Pad" at 47.917,-37.349 h0.98
  text "(Mixed)" at 57.825,-37.349 h0.98
  text "(Mixed)" at 70.275,-37.349 h0.98
  text "6" at -32.26,-39.795 h0.98
  text "1.143mm (45.00mil)" at -22.298,-39.795 h0.98
  text "PTH" at -3.373,-39.795 h0.98
  text "Round" at 5.166,-39.795 h0.98
  text "Top Layer-L1 - Bottom Layer-L6" at 17.42,-39.795 h0.98
  text "Pad" at 47.917,-39.795 h0.98
  text "(Mixed)" at 57.825,-39.795 h0.98
  text "(Mixed)" at 70.275,-39.795 h0.98
  text "M" at -41.335,-40.048 h1.09
  text "16" at -32.26,-42.24 h0.98
  text "0.900mm (35.43mil)" at -22.298,-42.24 h0.98
  text "PTH" at -3.373,-42.24 h0.98
  text "Round" at 5.166,-42.24 h0.98
  text "Top Layer-L1 - Bottom Layer-L6" at 17.42,-42.24 h0.98
  text "Pad" at 47.917,-42.24 h0.98
  text "(Mixed)" at 57.825,-42.24 h0.98
  text "(Mixed)" at 70.275,-42.24 h0.98
  text "20" at -32.26,-44.686 h0.98
  text "0.980mm (38.58mil)" at -22.298,-44.686 h0.98
  text "PTH" at -3.373,-44.686 h0.98
  text "Round" at 5.166,-44.686 h0.98
  text "Top Layer-L1 - Bottom Layer-L6" at 17.42,-44.686 h0.98
  text "Pad" at 47.917,-44.686 h0.98
  text "(Mixed)" at 57.825,-44.686 h0.98
  text "(Mixed)" at 70.275,-44.686 h0.98
  text "24" at -32.26,-47.131 h0.98
  text "1.000mm (39.37mil)" at -22.298,-47.131 h0.98
  text "PTH" at -3.373,-47.131 h0.98
  text "Round" at 5.166,-47.131 h0.98
  text "Top Layer-L1 - Bottom Layer-L6" at 17.42,-47.131 h0.98
  text "Pad" at 47.917,-47.131 h0.98
  text "(Mixed)" at 57.825,-47.131 h0.98
  text "(Mixed)" at 70.275,-47.131 h0.98
  text "40" at -32.26,-49.577 h0.98
  text "1.150mm (45.28mil)" at -22.298,-49.577 h0.98
  text "PTH" at -3.373,-49.577 h0.98
  text "Round" at 5.166,-49.577 h0.98
  text "Top Layer-L1 - Bottom Layer-L6" at 17.42,-49.577 h0.98
  text "Pad" at 47.917,-49.577 h0.98
  text "(Mixed)" at 57.825,-49.577 h0.98
  text "(Mixed)" at 70.275,-49.577 h0.98
  text "391" at -32.26,-52.022 h0.98
  text "0.250mm (9.84mil)" at -22.298,-52.022 h0.98
  text "PTH" at -3.373,-52.022 h0.98
  text "Round" at 5.166,-52.022 h0.98
  text "Top Layer-L1 - Bottom Layer-L6" at 17.42,-52.022 h0.98
  text "Via" at 47.917,-52.022 h0.98
  text "Rounded" at 57.825,-52.022 h0.98
  text "v56h25" at 70.275,-52.022 h0.98
  text "A" at -41.335,-52.276 h1.09
  text "525 Total" at -32.26,-54.468 h0.98
  text "Slot definitions :" at -40.798,-57.013 h0.98
  text "Routed Path Length" at -23.707,-57.013 h0.98
  text "= Calculated from tool start centre position to tool end centre position." at -5.475,-57.013 h0.98
  text "Hole Length" at -23.707,-58.825 h0.98
  text "= Routed Path Length + Tool Size = Slot length as defined in the PCB layout" at -12.157,-58.825 h0.98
